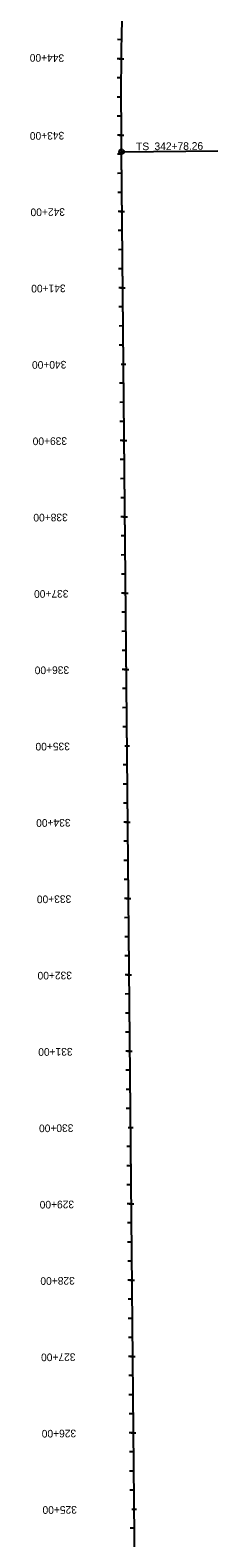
# Model space of a CAD drawing. Extents: x 23417911 to 23421158, y 6737892 to 6791804.
# Drawn here: x 23418104 to 23418350, y 6758944 to 6760918 of the extents above; entities that cross this region are included whole.
import ezdxf

# ---------------------------------------------------------------- set-up
doc = ezdxf.new("R2010")
doc.units = 0
for name, color, linetype in [('Alignment', 7, 'Continuous'), ('TextAlignment', 7, 'Continuous'), ('TextAlignmentLrg', 7, 'Continuous'), ('TextAlignmentSml', 7, 'Continuous')]:
    doc.layers.add(name, color=color, linetype=linetype)

msp = doc.modelspace()

# ---------------------------------------------------------------- linework, layer by layer
at = {"layer": 'Alignment'}
for q in [(23418223.8, 6760759.2), (23418223.8, 6760759.2), (23418223.8, 6760758.6)]:
    msp.add_line((23418258.6, 6756979.4), q, dxfattribs=at)
msp.add_open_spline([(23418223.8, 6760759.2), (23418223.8, 6760766.2), (23418223.6, 6760780), (23418223.4, 6760807.8), (23418223.3, 6760842.5), (23418223.5, 6760884.2), (23418224.3, 6760925.9), (23418225.7, 6760960.6), (23418227.3, 6760988.3), (23418228.3, 6761002.2), (23418228.8, 6761009.1)], degree=3, dxfattribs=at)
msp.add_open_spline([(23418223.8, 6760759.2), (23418223.8, 6760766.2), (23418223.6, 6760780), (23418223.4, 6760807.8), (23418223.3, 6760842.5), (23418223.5, 6760884.2), (23418224.3, 6760925.9), (23418225.7, 6760960.6), (23418227.3, 6760988.3), (23418228.3, 6761002.2), (23418228.8, 6761009.1)], degree=3, dxfattribs=at)
at = {"layer": 'TextAlignment'}
for p in [(23418223.8, 6760759.2), (23418349.8, 6760760.4)]:
    msp.add_line(p, (23418349.8, 6760760.4), dxfattribs=at)
msp.add_circle((23418223.8, 6760759.2), 3.12, dxfattribs=at)
at = {"layer": 'TextAlignmentLrg'}
for p, q in [((23418223.6, 6760880.9), (23418218.1, 6760881)), ((23418223.6, 6760781), (23418218.2, 6760780.9)), ((23418224.6, 6760681), (23418219.1, 6760680.9)), ((23418225.5, 6760581), (23418220, 6760580.9)), ((23418223.3, 6760480.9), (23418229.5, 6760481)), ((23418227.3, 6760381), (23418221.9, 6760380.9)), ((23418228.2, 6760281), (23418222.8, 6760280.9)), ((23418229.2, 6760181), (23418223.7, 6760180.9)), ((23418230.1, 6760081), (23418224.6, 6760080.9)), ((23418227.9, 6759981), (23418234.1, 6759981)), ((23418231.9, 6759881), (23418226.5, 6759880.9)), ((23418232.8, 6759781), (23418227.4, 6759780.9)), ((23418233.8, 6759681), (23418228.3, 6759680.9)), ((23418234.7, 6759581), (23418229.2, 6759581)), ((23418232.5, 6759481), (23418238.7, 6759481)), ((23418236.5, 6759381), (23418231.1, 6759381)), ((23418237.4, 6759281), (23418232, 6759281)), ((23418238.4, 6759181), (23418232.9, 6759181)), ((23418239.3, 6759081), (23418233.8, 6759081)), ((23418237.1, 6758981), (23418243.3, 6758981.1))]:
    msp.add_line(p, q, dxfattribs=at)
at = {"layer": 'TextAlignmentSml'}
for p, q in [((23418224, 6760905.9), (23418218.5, 6760906.1)), ((23418220.5, 6760881), (23418226.6, 6760880.9)), ((23418223.4, 6760855.9), (23418217.9, 6760856)), ((23418223.4, 6760830.9), (23418217.9, 6760830.9)), ((23418223.5, 6760805.9), (23418218, 6760805.9)), ((23418220.6, 6760780.9), (23418226.7, 6760781)), ((23418223.9, 6760756), (23418218.4, 6760755.9)), ((23418224.1, 6760731), (23418218.6, 6760730.9)), ((23418224.3, 6760706), (23418218.9, 6760705.9)), ((23418221.5, 6760680.9), (23418227.6, 6760681)), ((23418224.8, 6760656), (23418219.3, 6760655.9)), ((23418225, 6760631), (23418219.6, 6760630.9)), ((23418225.3, 6760606), (23418219.8, 6760605.9)), ((23418222.4, 6760580.9), (23418228.5, 6760581)), ((23418225.7, 6760556), (23418220.3, 6760555.9)), ((23418225.9, 6760531), (23418220.5, 6760530.9)), ((23418226.2, 6760506), (23418220.7, 6760505.9)), ((23418223.3, 6760480.9), (23418229.5, 6760481)), ((23418226.6, 6760456), (23418221.2, 6760455.9)), ((23418226.9, 6760431), (23418221.4, 6760430.9)), ((23418227.1, 6760406), (23418221.6, 6760405.9)), ((23418224.3, 6760380.9), (23418230.4, 6760381)), ((23418227.6, 6760356), (23418222.1, 6760355.9)), ((23418227.8, 6760331), (23418222.3, 6760330.9)), ((23418228, 6760306), (23418222.6, 6760305.9)), ((23418225.2, 6760280.9), (23418231.3, 6760281)), ((23418228.5, 6760256), (23418223, 6760255.9)), ((23418228.7, 6760231), (23418223.2, 6760230.9)), ((23418228.9, 6760206), (23418223.5, 6760205.9)), ((23418226.1, 6760180.9), (23418232.2, 6760181)), ((23418229.4, 6760156), (23418223.9, 6760155.9)), ((23418229.6, 6760131), (23418224.2, 6760130.9)), ((23418229.9, 6760106), (23418224.4, 6760105.9)), ((23418227, 6760081), (23418233.1, 6760081)), ((23418230.3, 6760056), (23418224.9, 6760055.9)), ((23418230.5, 6760031), (23418225.1, 6760030.9)), ((23418230.8, 6760006), (23418225.3, 6760005.9)), ((23418227.9, 6759981), (23418234.1, 6759981)), ((23418231.2, 6759956), (23418225.8, 6759955.9)), ((23418231.5, 6759931), (23418226, 6759930.9)), ((23418231.7, 6759906), (23418226.2, 6759905.9)), ((23418228.9, 6759881), (23418235, 6759881)), ((23418232.2, 6759856), (23418226.7, 6759855.9)), ((23418232.4, 6759831), (23418226.9, 6759830.9)), ((23418232.6, 6759806), (23418227.2, 6759805.9)), ((23418229.8, 6759781), (23418235.9, 6759781)), ((23418233.1, 6759756), (23418227.6, 6759755.9)), ((23418233.3, 6759731), (23418227.8, 6759730.9)), ((23418233.5, 6759706), (23418228.1, 6759705.9)), ((23418230.7, 6759681), (23418236.8, 6759681)), ((23418234, 6759656), (23418228.5, 6759655.9)), ((23418234.2, 6759631), (23418228.8, 6759630.9)), ((23418234.5, 6759606), (23418229, 6759605.9)), ((23418231.6, 6759581), (23418237.7, 6759581)), ((23418234.9, 6759556), (23418229.5, 6759556)), ((23418235.1, 6759531), (23418229.7, 6759531)), ((23418235.4, 6759506), (23418229.9, 6759506)), ((23418232.5, 6759481), (23418238.7, 6759481)), ((23418235.8, 6759456), (23418230.4, 6759456)), ((23418236.1, 6759431), (23418230.6, 6759431)), ((23418236.3, 6759406), (23418230.8, 6759406)), ((23418233.5, 6759381), (23418239.6, 6759381)), ((23418236.8, 6759356), (23418231.3, 6759356)), ((23418237, 6759331), (23418231.5, 6759331)), ((23418237.2, 6759306), (23418231.8, 6759306)), ((23418234.4, 6759281), (23418240.5, 6759281)), ((23418237.7, 6759256), (23418232.2, 6759256)), ((23418237.9, 6759231), (23418232.4, 6759231)), ((23418238.1, 6759206), (23418232.7, 6759206)), ((23418235.3, 6759181), (23418241.4, 6759181)), ((23418238.6, 6759156), (23418233.1, 6759156)), ((23418238.8, 6759131), (23418233.4, 6759131)), ((23418239.1, 6759106), (23418233.6, 6759106)), ((23418236.2, 6759081), (23418242.3, 6759081.1)), ((23418239.5, 6759056), (23418234.1, 6759056)), ((23418239.7, 6759031), (23418234.3, 6759031)), ((23418240, 6759006), (23418234.5, 6759006)), ((23418237.1, 6758981), (23418243.3, 6758981.1)), ((23418240.4, 6758956), (23418235, 6758956))]:
    msp.add_line(p, q, dxfattribs=at)

# ---------------------------------------------------------------- texts
at = {"layer": 'TextAlignment'}
for s, p in [('TS', (23418242.8, 6760761.1)), ('342+78.26', (23418266.9, 6760761.3))]:
    msp.add_text(s, height=10.02, rotation=0.5274, dxfattribs=at).set_placement(p)
at = {"layer": 'TextAlignmentLrg'}
for s, p in [('340+00', (23418151.4, 6760485.3)), ('335+00', (23418156, 6759985.3)), ('330+00', (23418160.6, 6759485.3)), ('325+00', (23418165.2, 6758985.3))]:
    msp.add_text(s, height=10.02, rotation=180.5274, dxfattribs=at).set_placement(p)
at = {"layer": 'TextAlignmentSml'}
for s, rotation, p in [('344+00', 179.3417, (23418148.6, 6760886.8)), ('343+00', 180.4896, (23418148.6, 6760785.3)), ('342+00', 180.5274, (23418149.5, 6760685.3)), ('341+00', 180.5274, (23418150.4, 6760585.3)), ('340+00', 180.5274, (23418151.4, 6760485.3)), ('339+00', 180.5274, (23418152.3, 6760385.3)), ('338+00', 180.5274, (23418153.2, 6760285.3)), ('337+00', 180.5274, (23418154.1, 6760185.3)), ('336+00', 180.5274, (23418155, 6760085.3)), ('335+00', 180.5274, (23418156, 6759985.3)), ('334+00', 180.5274, (23418156.9, 6759885.3)), ('333+00', 180.5274, (23418157.8, 6759785.3)), ('332+00', 180.5274, (23418158.7, 6759685.3)), ('331+00', 180.5274, (23418159.6, 6759585.3)), ('330+00', 180.5274, (23418160.6, 6759485.3)), ('329+00', 180.5274, (23418161.5, 6759385.3)), ('328+00', 180.5274, (23418162.4, 6759285.3)), ('327+00', 180.5274, (23418163.3, 6759185.3)), ('326+00', 180.5274, (23418164.2, 6759085.3)), ('325+00', 180.5274, (23418165.2, 6758985.3))]:
    msp.add_text(s, height=10.02, rotation=rotation, dxfattribs=at).set_placement(p)

doc.saveas('drawing.dxf')
